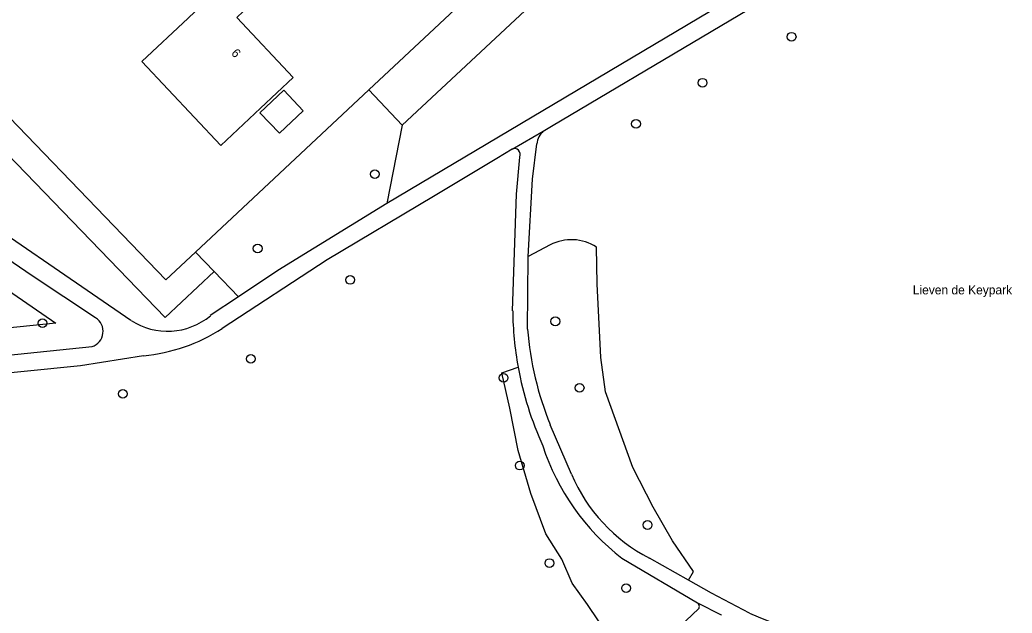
# Model space of a CAD drawing. Extents: x 159353 to 160616, y 385893 to 387321.
# Drawn here: x 160022.1 to 160132.8, y 386230.6 to 386296.8 of the extents above; entities that cross this region are included whole.
import ezdxf

# ---------------------------------------------------------------- set-up
doc = ezdxf.new("R2010")
doc.units = 0
for name, color, linetype in [('IMGEO_Boom', 7, 'Continuous'), ('IMGEO_Groenvoorziening', 7, 'Continuous'), ('IMGEO_Openbare_ruimte_label', 7, 'Continuous'), ('IMGEO_Pand', 7, 'Continuous'), ('IMGEO_Pand_nummerreeks', 7, 'Continuous'), ('IMGEO_Voetpad_halfverhard', 7, 'Continuous')]:
    doc.layers.add(name, color=color, linetype=linetype)

msp = doc.modelspace()

# ---------------------------------------------------------------- linework, layer by layer
at = {"layer": 'IMGEO_Boom'}
for centre in [(160108.23, 386294.9), (160098.3, 386289.77), (160090.87, 386285.19), (160061.74, 386279.57), (160048.66, 386271.28), (160058.98, 386267.77), (160024.66, 386262.95), (160081.87, 386263.15), (160047.9, 386258.97), (160076.1, 386256.85), (160033.62, 386255.07), (160084.58, 386255.74), (160077.9, 386247.06), (160092.16, 386240.43), (160081.21, 386236.18), (160089.76, 386233.38)]:
    msp.add_circle(centre, 0.489, dxfattribs=at)
at = {"layer": 'IMGEO_Groenvoorziening'}
for points in [[(160072.22, 386332.32), (160088.65, 386314.8), (160061.08, 386288.98)], [(160064.79, 386285.02), (160091.62, 386310.11), (160092.96, 386312.09), (160094.09, 386314.2), (160095, 386316.41), (160095.67, 386318.7), (160096.07, 386320.86)], [(160014.16, 386292.91), (160038.43, 386267.78), (160041.72, 386270.86)], [(160043.8, 386268.7), (160038.33, 386263.57), (160013.44, 386289.35)], [(160041.72, 386270.86), (160061.08, 386288.98)], [(160061.08, 386288.98), (160064.79, 386285.02)], [(160064.79, 386285.02), (160063.06, 386276.3)], [(160011.26, 386261.44), (160013.29, 386271.79), (160026.14, 386262.95), (160011.26, 386261.44)], [(160043.8, 386268.7), (160041.72, 386270.86)], [(160081.3, 386271.69), (160078.85, 386270.38)], [(160096.72, 386234.29), (160097.28, 386235.24), (160094.94, 386238.66), (160092.77, 386242.43), (160090.52, 386246.83), (160087.45, 386255.28), (160086.95, 386259.11), (160086.55, 386267.34), (160086.46, 386271.44)], [(160046.52, 386265.88), (160043.8, 386268.7)], [(160090.9, 386224.48), (160087.99, 386227.79), (160085.47, 386231.57), (160083.73, 386233.95), (160082.58, 386236.61), (160080.82, 386239.45), (160079.13, 386243.93), (160077.71, 386248.74), (160076.79, 386253.47), (160075.91, 386257.42), (160077.71, 386258.04)]]:
    msp.add_lwpolyline(points, dxfattribs=at)
msp.add_arc((160083.66, 386267.05), 5.21, 57.4833, 116.9923, dxfattribs=at)
at = {"layer": 'IMGEO_Pand'}
for points in [[(160052.62, 386290.35), (160048.98, 386286.92), (160044.56, 386282.76), (160035.73, 386292.14), (160040.89, 386296.99), (160044.52, 386300.42), (160047.05, 386297.73), (160046.35, 386297.05), (160052.62, 386290.35)], [(160051.08, 386284.13), (160053.74, 386286.64), (160051.57, 386288.94), (160048.91, 386286.43), (160051.08, 386284.13)]]:
    msp.add_lwpolyline(points, dxfattribs=at)
at = {"layer": 'IMGEO_Voetpad_halfverhard'}
for points in [[(160114.21, 386306.72), (160106.89, 386302.36), (160102.81, 386299.94), (160063.06, 386276.3)], [(160080.53, 386284.38), (160081.43, 386284.91), (160117.07, 386306.09)], [(160077.07, 386282.35), (160077.07, 386282.36), (160080.53, 386284.38)], [(160078.85, 386270.38), (160079.32, 386279), (160079.82, 386282.96)], [(160077.07, 386282.35), (160075.35, 386281.3), (160068.28, 386277.08), (160056.43, 386270), (160044.71, 386262.35)], [(160077.11, 386264.32), (160077.52, 386277.34), (160077.91, 386281.48)], [(160034.53, 386263.25), (160013.69, 386277.51)], [(160063.06, 386276.3), (160050.9, 386268.81), (160046.52, 386265.88)], [(160030.58, 386263.54), (160023.49, 386268.24), (160014.89, 386274.11), (160014.44, 386274.42), (160013.72, 386274.85), (160013.46, 386274.97)], [(160078.76, 386262.27), (160078.84, 386270.3), (160078.85, 386270.38)], [(160046.52, 386265.88), (160043.38, 386263.79)], [(160010.24, 386258.32), (160016.1, 386258.91), (160024.07, 386259.72), (160030.19, 386260.35)], [(160035.93, 386259.31), (160028.88, 386258.19), (160010.36, 386256.33)], [(160083.68, 386246.1), (160081.28, 386251.62)], [(160089.29, 386236.72), (160097.72, 386231.75)], [(160096.72, 386234.29), (160092.36, 386236.74)], [(160103.52, 386230.6), (160099.3, 386232.83), (160096.72, 386234.29)], [(160097.86, 386231.09), (160090.9, 386224.48)], [(160097.72, 386231.75), (160100.38, 386230.4), (160100.39, 386230.38)]]:
    msp.add_lwpolyline(points, dxfattribs=at)
for centre, radius, start, end in [((160081.96, 386282.77), 2.15, 131.7244, 175.0486), ((160077.36, 386281.92), 0.522, 38.7717, 123.5875), ((160077.17, 386281.74), 0.78, 341.1264, 40.6223), ((160113.89, 386264.71), 36.78, 180.6062, 190.45), ((160029.64, 386262.03), 1.78, 288.1502, 58.0723), ((160038.6, 386269.48), 7.44, 236.8522, 310.0158), ((160033.95, 386279.22), 20.01, 275.6542, 302.5211), ((160115.52, 386265.37), 36.89, 184.8097, 201.8769), ((160114.61, 386264.81), 37.51, 190.403, 204.4894), ((160105.22, 386257.3), 26.02, 197.9885, 232.2546), ((160100.84, 386253.31), 18.61, 202.789, 242.8987), ((160097.49, 386231.35), 0.454, 324.1266, 60.0273), ((160122.83, 386273.57), 47.11, 245.8063, 266.5231)]:
    msp.add_arc(centre, radius, start, end, dxfattribs=at)

# ---------------------------------------------------------------- texts
at = {"layer": 'IMGEO_Openbare_ruimte_label'}
msp.add_text('Lieven de Keypark', height=1, dxfattribs=at).set_placement((160121.75, 386266.16))
at = {"layer": 'IMGEO_Pand_nummerreeks'}
msp.add_text('6', height=1, rotation=313.11, dxfattribs=at).set_placement((160045.64, 386293.01))

doc.saveas('drawing.dxf')
